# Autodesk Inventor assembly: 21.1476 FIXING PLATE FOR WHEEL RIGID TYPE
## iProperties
Created: 2007-04
Part Number: 21.1476 FIXING PLATE FOR WHEEL RIGID TYPE
Document SubType Name: Assembly
Designer: Andy Moles
Author: Andy Moles
